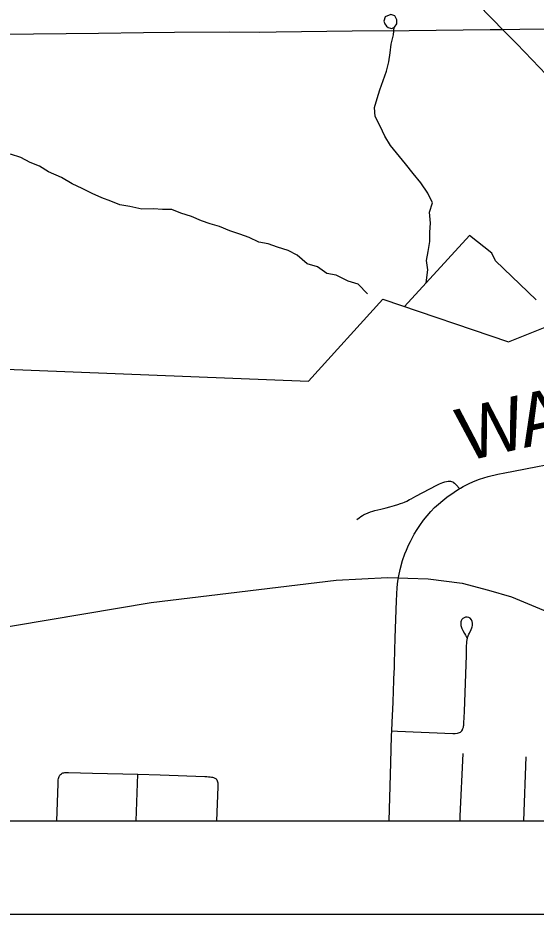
# Model space of a CAD drawing. Extents: x 0 to 34, y 0 to 22.
# Drawn here: x 24.284 to 24.841, y 13.024 to 13.986 of the extents above; entities that cross this region are included whole.
import ezdxf

# ---------------------------------------------------------------- set-up
doc = ezdxf.new("R2010")
doc.units = 0
for name, color, linetype in [('GM_X_Corporation', 7, 'Continuous'), ('GM_X_County_Road', 7, 'Continuous'), ('GM_X_County_Road_Text', 7, 'Continuous'), ('GM_X_Minor_Lake', 7, 'Continuous'), ('GM_X_Minor_River', 7, 'Continuous'), ('GM_X_Rail_Line', 7, 'Continuous'), ('GM_X_Township_Road', 7, 'Continuous'), ('SH_Data', 7, 'Continuous')]:
    doc.layers.add(name, color=color, linetype=linetype)

msp = doc.modelspace()

# ---------------------------------------------------------------- linework, layer by layer
at = {"layer": 'GM_X_Corporation'}
msp.add_lwpolyline([(23.44381, 15.60337), (23.44381, 13.12386), (28.80084, 13.12386)], dxfattribs=at)
at = {"layer": 'GM_X_County_Road'}
for points in [[(24.80457, 13.97386), (24.79456, 13.98403), (24.77577, 14.00299), (24.76063, 14.01855), (24.74635, 14.03327), (24.72773, 14.05246), (24.71728, 14.06389), (24.71509, 14.0665), (24.71251, 14.06988), (24.7105, 14.07286), (24.70904, 14.07511), (24.70787, 14.07717), (24.70687, 14.07942), (24.70607, 14.08178), (24.70558, 14.08381), (24.70525, 14.08589), (24.70502, 14.08982)], [(24.26599, 13.96876), (24.3705, 13.96976), (24.41876, 13.97038), (24.45216, 13.97084), (24.51109, 13.97114), (24.54335, 13.97103), (24.56131, 13.97132), (24.64315, 13.9725), (24.70407, 13.97276), (24.79141, 13.97376), (24.80457, 13.97386)], [(24.80457, 13.97386), (24.82312, 13.97401), (24.86518, 13.97434), (24.91564, 13.97506), (24.96621, 13.9754), (25.04727, 13.9761), (25.10574, 13.97657), (25.14891, 13.97651)], [(24.96794, 13.80568), (24.95584, 13.81834), (24.93547, 13.83931), (24.91808, 13.85708), (24.90074, 13.87489), (24.88419, 13.89173), (24.8682, 13.90827), (24.85122, 13.92558), (24.83617, 13.94124), (24.81985, 13.95833), (24.80457, 13.97386)], [(24.75834, 13.4807), (24.75938, 13.48128), (24.76221, 13.48292), (24.76808, 13.48587), (24.77327, 13.48828), (24.77988, 13.49079), (24.78901, 13.49376), (24.7993, 13.49623), (24.80695, 13.49781), (24.81646, 13.49958), (24.84212, 13.50441), (24.86468, 13.50889), (24.88981, 13.51403), (24.89526, 13.51524), (24.9007, 13.51653), (24.90459, 13.51758), (24.90804, 13.51867), (24.91139, 13.51984), (24.91511, 13.52127), (24.92053, 13.52354), (24.92953, 13.52795), (24.94952, 13.53936)], [(24.70626, 13.46986), (24.71154, 13.47277), (24.7338, 13.48433), (24.73698, 13.48583), (24.74028, 13.48722), (24.74255, 13.48802), (24.74421, 13.48845), (24.74602, 13.48867), (24.74671, 13.48873), (24.74791, 13.48873), (24.74856, 13.4887), (24.74975, 13.48848), (24.75111, 13.48793), (24.75166, 13.4876), (24.75282, 13.48662), (24.75477, 13.48463), (24.75834, 13.4807)], [(24.688, 13.28054), (24.6883, 13.29072), (24.68838, 13.29317), (24.68923, 13.32047), (24.69053, 13.36022), (24.69136, 13.37445), (24.69217, 13.38125), (24.6931, 13.38705), (24.69451, 13.39391), (24.69714, 13.40343), (24.69963, 13.41056), (24.70129, 13.41482), (24.70353, 13.41996), (24.70551, 13.42406), (24.70776, 13.42838), (24.70976, 13.43188), (24.71276, 13.43679), (24.71557, 13.44104), (24.71978, 13.44699), (24.72356, 13.45161), (24.72752, 13.45612), (24.73159, 13.46036), (24.73582, 13.46417), (24.74022, 13.46787), (24.7448, 13.47146), (24.74836, 13.47409), (24.75111, 13.47603), (24.7541, 13.47805), (24.75594, 13.47923), (24.75834, 13.4807)], [(24.64805, 13.44772), (24.65035, 13.44947), (24.65226, 13.45083), (24.65403, 13.45195), (24.65527, 13.45263), (24.65664, 13.45334), (24.65764, 13.4538), (24.66023, 13.45489), (24.66279, 13.45583), (24.66515, 13.45652), (24.66719, 13.45707), (24.67067, 13.45797), (24.67365, 13.45871), (24.67956, 13.46015), (24.68336, 13.46115), (24.68833, 13.46253), (24.69202, 13.46365), (24.69496, 13.46468), (24.69733, 13.46558), (24.69931, 13.46635), (24.70163, 13.46741), (24.7045, 13.46889), (24.70626, 13.46986)], [(24.68565, 13.22053), (24.68605, 13.22959), (24.68706, 13.2513), (24.68753, 13.26371), (24.68785, 13.27421), (24.68794, 13.2785), (24.688, 13.28054)], [(24.68292, 13.12386), (24.68435, 13.17373), (24.68465, 13.18615), (24.68543, 13.21535), (24.68565, 13.22053)]]:
    msp.add_lwpolyline(points, dxfattribs=at)
at = {"layer": 'GM_X_Minor_Lake'}
msp.add_line((24.67796, 13.97992), (24.68006, 13.97726), dxfattribs=at)
msp.add_lwpolyline([(24.68006, 13.97726), (24.68161, 13.97588), (24.68426, 13.97514), (24.68578, 13.97477), (24.68842, 13.97631), (24.69104, 13.97974), (24.69101, 13.98429), (24.6887, 13.98844), (24.68453, 13.98993), (24.67849, 13.98723), (24.67702, 13.98267), (24.67796, 13.97992)], dxfattribs=at)
at = {"layer": 'GM_X_Minor_River'}
for p, q in [((24.7689, 13.75245), (24.69909, 13.67636)), ((24.7929, 13.73368), (24.7689, 13.75245)), ((24.79713, 13.72537), (24.7929, 13.73368)), ((24.84055, 13.68346), (24.79713, 13.72537)), ((24.59603, 13.59603), (24.67596, 13.68424)), ((24.67596, 13.68424), (24.81106, 13.63825)), ((24.81106, 13.63825), (24.86491, 13.65995)), ((24.22537, 13.61099), (24.59603, 13.59603))]:
    msp.add_line(p, q, dxfattribs=at)
for points in [[(24.72248, 13.70185), (24.72415, 13.7157), (24.72294, 13.72555), (24.72476, 13.73543), (24.72657, 13.74606), (24.72648, 13.7563), (24.72717, 13.76578), (24.72594, 13.77753), (24.72927, 13.78779), (24.72427, 13.79799), (24.71661, 13.80893), (24.70858, 13.8191), (24.70017, 13.82966), (24.68412, 13.84925), (24.67799, 13.85906), (24.67298, 13.87002), (24.6676, 13.88022), (24.66715, 13.89007), (24.66972, 13.89957), (24.67267, 13.90907), (24.67638, 13.91896), (24.67971, 13.92885), (24.68228, 13.9391), (24.68372, 13.94859), (24.68478, 13.95808), (24.68735, 13.96796), (24.68827, 13.97623)], [(24.65964, 13.6898), (24.64933, 13.70034), (24.63871, 13.70367), (24.62579, 13.71002), (24.61594, 13.71184), (24.60566, 13.71896), (24.59466, 13.72229), (24.58399, 13.73131), (24.57411, 13.73654), (24.56273, 13.73987), (24.55286, 13.74358), (24.54263, 13.7454), (24.53237, 13.75025), (24.5225, 13.75397), (24.51149, 13.75767), (24.50048, 13.76214), (24.49062, 13.7651), (24.48113, 13.76844), (24.4705, 13.77291), (24.45911, 13.77661), (24.44924, 13.78033), (24.4394, 13.78063), (24.42956, 13.78131), (24.41707, 13.78084), (24.40418, 13.78377), (24.39357, 13.78558), (24.3837, 13.7893), (24.3742, 13.79302), (24.36357, 13.79749), (24.35293, 13.80309), (24.34229, 13.80794), (24.33089, 13.81468), (24.31683, 13.82102), (24.30732, 13.82701), (24.29707, 13.8311), (24.28719, 13.83633), (24.27619, 13.84004)]]:
    msp.add_lwpolyline(points, dxfattribs=at)
at = {"layer": 'GM_X_Rail_Line'}
msp.add_lwpolyline([(23.44381, 13.3271), (23.521, 13.31215), (23.6525, 13.29246), (23.70823, 13.28473), (23.75761, 13.27949), (23.8057, 13.2772), (23.84696, 13.27802), (23.88857, 13.28157), (23.9419, 13.28973), (23.98688, 13.29785), (24.08722, 13.30831), (24.24377, 13.32768), (24.42723, 13.35829), (24.62573, 13.38259), (24.68089, 13.38534), (24.72463, 13.38394), (24.76114, 13.37909), (24.78933, 13.3718), (24.8141, 13.36445), (24.8529, 13.34856), (25.26415, 13.16081), (25.33926, 13.12386)], dxfattribs=at)
at = {"layer": 'GM_X_Township_Road'}
for p, q in [((24.82728, 13.12386), (24.82983, 13.1928)), ((24.41108, 13.12386), (24.41288, 13.17404))]:
    msp.add_line(p, q, dxfattribs=at)
for points in [[(24.76019, 13.21997), (24.76074, 13.22066), (24.76135, 13.22161), (24.76167, 13.22221), (24.76203, 13.22313), (24.76221, 13.22376), (24.76244, 13.22468), (24.76261, 13.2255), (24.76281, 13.22686), (24.76291, 13.22787), (24.76303, 13.22943), (24.76338, 13.23454), (24.76375, 13.24185), (24.7657, 13.30145), (24.76594, 13.31192), (24.76608, 13.31487), (24.76614, 13.3158), (24.76626, 13.31732), (24.76636, 13.31806), (24.76653, 13.31906), (24.76671, 13.31995), (24.767, 13.32091), (24.76758, 13.32262), (24.76833, 13.32442), (24.76893, 13.32567), (24.77089, 13.32941), (24.77163, 13.33122), (24.77194, 13.33231), (24.77221, 13.33385), (24.77227, 13.33516), (24.77224, 13.33642), (24.77201, 13.33787), (24.77117, 13.33988), (24.76981, 13.34145), (24.76846, 13.34228), (24.76667, 13.34272), (24.7649, 13.34263), (24.76324, 13.34213), (24.76186, 13.34126), (24.76094, 13.3403), (24.76052, 13.33964), (24.76007, 13.33877), (24.75973, 13.33766), (24.75963, 13.33693), (24.75959, 13.33552), (24.75969, 13.33458), (24.75983, 13.33372), (24.76007, 13.33284), (24.76049, 13.33165), (24.76088, 13.33069), (24.76195, 13.32842), (24.76367, 13.32504), (24.76461, 13.32331), (24.76611, 13.32068)], [(24.68565, 13.22053), (24.69183, 13.22025), (24.7512, 13.21791), (24.75372, 13.2179), (24.75607, 13.21808), (24.75728, 13.21832), (24.75845, 13.21871), (24.75942, 13.21927), (24.76019, 13.21997)], [(24.75893, 13.12386), (24.75914, 13.12893), (24.76225, 13.19639)], [(24.32579, 13.12386), (24.32713, 13.16357), (24.3272, 13.16614), (24.32732, 13.16784), (24.32752, 13.16939), (24.32786, 13.17051), (24.32824, 13.17153), (24.32907, 13.17287), (24.32981, 13.17375), (24.33069, 13.17451)], [(24.33069, 13.17451), (24.33158, 13.17502), (24.33236, 13.17536), (24.33316, 13.1756), (24.33441, 13.17576), (24.33572, 13.1758), (24.33661, 13.1758), (24.33821, 13.17578), (24.36411, 13.17523), (24.41288, 13.17404)], [(24.41288, 13.17404), (24.4366, 13.17341), (24.48472, 13.17159), (24.48687, 13.17147), (24.48858, 13.17135), (24.48993, 13.17121), (24.49064, 13.17112), (24.49174, 13.17095), (24.49283, 13.17077), (24.49391, 13.17053), (24.49479, 13.17024), (24.49565, 13.16981), (24.4968, 13.169), (24.49743, 13.16842)], [(24.49747, 13.12386), (24.49901, 13.16065), (24.49905, 13.16221), (24.49903, 13.16323), (24.49894, 13.16435), (24.4988, 13.16537), (24.4985, 13.16655), (24.49801, 13.16757), (24.49743, 13.16842)]]:
    msp.add_lwpolyline(points, dxfattribs=at)
at = {"layer": 'SH_Data'}
for p, q in [((23.44381, 13.12386), (30.24381, 13.12386)), ((23.34381, 13.02386), (30.34381, 13.02386))]:
    msp.add_line(p, q, dxfattribs=at)

# ---------------------------------------------------------------- texts
at = {"layer": 'GM_X_County_Road_Text'}
for s, rotation, p in [('W', 13.04915, (24.7637, 13.50952)), ('A', 12.10366, (24.82759, 13.52433))]:
    msp.add_text(s, height=0.05682, rotation=rotation, dxfattribs=at).set_placement(p)

doc.saveas('drawing.dxf')
